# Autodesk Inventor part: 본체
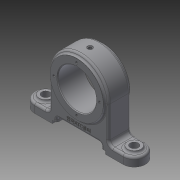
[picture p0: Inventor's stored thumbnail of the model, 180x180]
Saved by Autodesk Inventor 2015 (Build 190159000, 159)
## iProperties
Created: 2019-05
Part Number: 본체
Material: 일반
Document SubType Name: Modeling
Designer: now
Density: 1 g/cm^3
Appearance: 기본값
Author: now
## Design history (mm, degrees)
sketch "스케치1"
  geometry: L1 (-75, 15)-(75, 15); L2 (75, 15)-(75, -15); L3 (75, -15)-(-75, -15); L4 (-75, -15)-(-75, 15); L5 (-75, 15)-(75, -15); L6 (75, 15)-(-75, -15); 1 further point
  constraints: 12 end point, 2 midpoint, 2 parallel, 1 horizontal, 1 perpendicular
  dimensions: "d0" = 150 distance of L2.end L3.end; "d1" = 30 distance of L1.end L2.end
extrude "돌출1" new body sketch "스케치1" distance "d2" = 12; taper "d3" = 0 deg
fillet "모깎기1" dims "d4" = 15
sketch "스케치2"
  geometry: L1 (120, 0)-(0, 0) reference; C1 r 40 at (60, 60); 2 further points
  constraints: 1 centre point, 1 midpoint, 1 vertical alignment
  dimensions: "d5" = 80 diameter of C1; "d6" = 60 distance of C1.centre point (60, 0)
extrude "돌출2" join sketch "스케치2" distance "d7" = 30; taper "d8" = 0 deg
sketch "스케치3"
  geometry: L1 (120, 0)-(0, 0) reference; L2 (0, 12)-(120, 12) reference; L3 (20, 12)-(100, 12); L4 (100, 12)-(100, 60); L5 (100, 60)-(20, 60); L6 (20, 60)-(20, 12); 3 further points
  constraints: 8 end point, 2 midpoint, 2 parallel, 1 horizontal, 1 perpendicular, 1 point on line, 1 vertical alignment
  dimensions: "d9" = 80 distance of L4.end L5.end; "d10" = 48 distance of L3.end L4.end
extrude "돌출3" join sketch "스케치3" distance "d11" = 30; taper "d12" = 0 deg
sketch "스케치4"
  geometry: A1 r 40 centre (60, 60) between (100, 60) and (20, 60) reference; 1 further point
hole "구멍1" sketch "스케치4" at (60, 60) diameter "d13" = 52; stored, may be unused: countersink angle "d17" = 90 deg, drill point angle "d19" = 118 deg; dims "d14" = 6, "d15" = 4, "d16" = 2, "d18" = 8
sketch "스케치5"
  geometry: C1 r 26 at (60, 60) reference; C2 r 36 at (60, 60); A1 r 40 centre (60, 60) between (100, 60) and (20, 60) reference; 1 further point
  constraints: 1 centre point, 1 coincident
  dimensions: "d20" = 72 diameter of C2
extrude "돌출4" join sketch "스케치5" distance "d21" = 3; taper "d22" = 0 deg
sketch "스케치6"
  geometry: C1 r 26 at (0, 0) reference; 2 further points
  constraints: 1 vertical alignment
  dimensions: "d23" = 31 distance of point (0, 31) C1.centre
hole "구멍2" sketch "스케치6" at (0, 31) diameter "d24" = 3.242; stored, may be unused: countersink angle "d28" = 90 deg, drill point angle "d30" = 118 deg; dims "d25" = 6, "d26" = 4, "d27" = 2, "d29" = 8
sketch "스케치7"
  geometry: C1 r 9 at (60, 0); A1 r 15 centre (60, 0) between (60, -15) and (60, 15) reference; 1 further point
  constraints: 1 centre point, 1 coincident
  dimensions: "d34" = 18 diameter of C1
extrude "돌출5" join sketch "스케치7" distance "d35" = 3; taper "d36" = 0 deg
sketch "스케치8"
  geometry: C1 r 9 at (0, 0) reference; 1 further point
hole "구멍3" sketch "스케치8" at (0, 0) diameter "d37" = 11; stored, may be unused: countersink angle "d41" = 90 deg, drill point angle "d43" = 118 deg; dims "d38" = 6, "d39" = 4, "d40" = 2, "d42" = 8
sketch "스케치9"
  geometry: L1 (-36, -60)-(36, -60); L2 (36, -60)-(36, -56); L3 (36, -56)-(-36, -56); L4 (-36, -56)-(-36, -60); 2 further points
  constraints: 8 end point, 2 parallel, 1 coincident, 1 horizontal, 1 midpoint, 1 perpendicular
  dimensions: "d44" = 72 distance of L1.start L1.end; "d45" = 4 distance of L1.end L2.end
extrude "돌출6" cut sketch "스케치9" stored distance "d46" = 3; taper "d47" = 0 deg
sketch "스케치11"
  geometry: L1 (-90, 0)-(-30, 0); L2 (-30, 0)-(-30, 10); L3 (-30, 10)-(-90, 10); L4 (-90, 10)-(-90, 0); 2 further points
  constraints: 8 end point, 2 parallel, 1 coincident, 1 horizontal, 1 midpoint, 1 perpendicular
  dimensions: "d52" = 60 distance of L1.start L1.end; "d53" = 10 distance of L1.end L2.end
extrude "돌출8" cut sketch "스케치11" stored distance "d54" = 3; taper "d55" = 0 deg
node "작업 평면1"
sketch "스케치13"
  geometry: 1 further point
hole "구멍4" sketch "스케치13" at (0, 0) diameter "d60" = 2; stored, may be unused: countersink angle "d64" = 90 deg, drill point angle "d66" = 118 deg; dims "d61" = 6, "d62" = 6, "d63" = 2, "d65" = 40
sketch "스케치14"
  geometry: 1 further point
hole "구멍5" sketch "스케치14" at (0, 0) diameter "d67" = 4.917; stored, may be unused: countersink angle "d71" = 90 deg, drill point angle "d73" = 118 deg; dims "d68" = 8, "d69" = 7, "d70" = 1, "d72" = 10
sketch "스케치15"
  geometry: C1 r 1.5 at (0, 26); 2 further points
  constraints: 2 vertical alignment, 1 centre point, 1 other
  dimensions: "d74" = 3 diameter of C1
extrude "돌출10" cut sketch "스케치15" stored distance "d75" = 1; taper "d76" = 0 deg
fillet "모깎기2" dims "d77" = 6
fillet "모깎기3" dims "d78" = 3
fillet "모깎기4" dims "d79" = 3
fillet "모깎기5" dims "d80" = 3
fillet "모깎기6" dims "d81" = 3
chamfer "모따기1" distance "d82" = 1; stored, may be unused: second distance "d83" = 2, angle "d84" = 45 deg
sketch "스케치16"
  geometry: L1 (33, 10)-(87, 10) reference; A1 r 39 centre (60, 60) between (23, 47.671) and (97, 47.671) reference; 2 further points
  constraints: 1 vertical alignment, 1 other
  dimensions: "d85" = 7 distance from line of point (60, 17) L1
feature "엠보싱1" sketch "스케치16" dims "d0" = 150, "d1" = 30, "d86" = 0.5, "d87" = 0
node "솔리드1"
mirror "대칭1"
pattern_circular "원형 패턴1" dims angle "d32" = 360 deg
mirror "대칭2"
mirror "대칭3"
